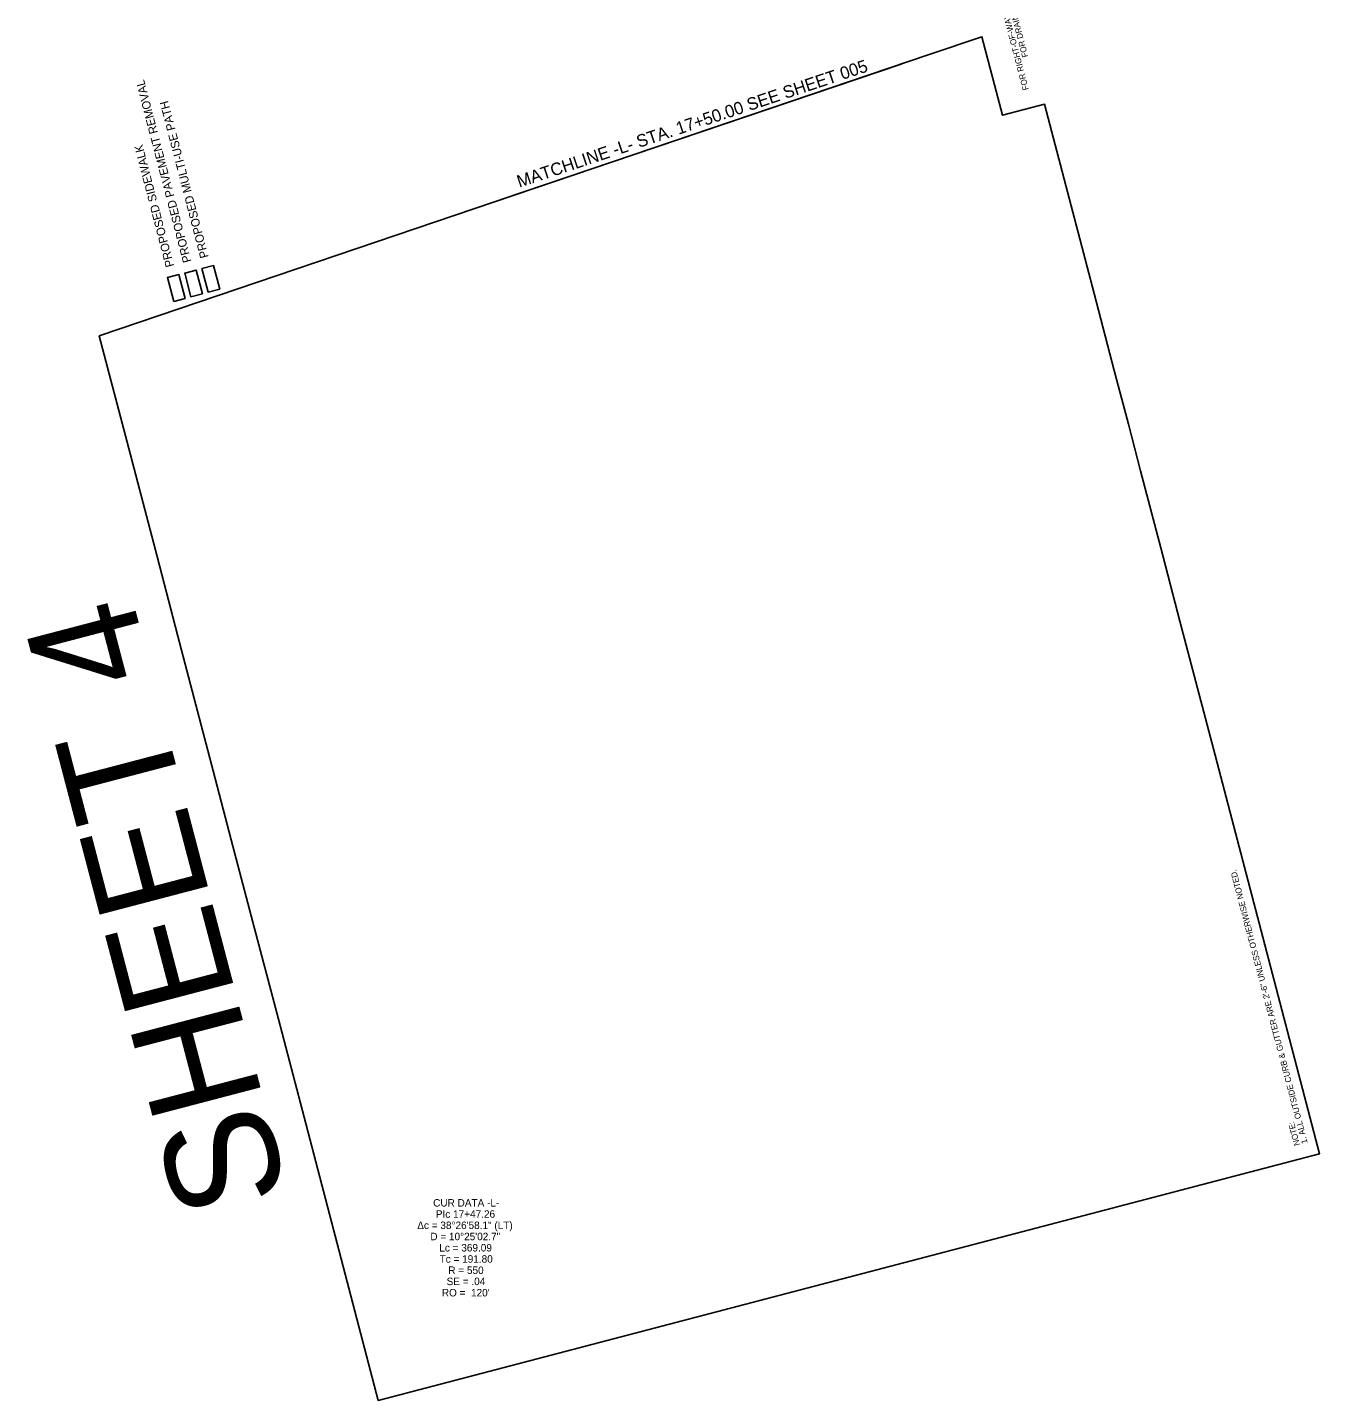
# Model space of a CAD drawing. Extents: x 1366798 to 1369150, y 878329 to 881399.
# Drawn here: x 1366798 to 1368093, y 878329 to 879705 of the extents above; entities that cross this region are included whole.
import ezdxf

# ---------------------------------------------------------------- set-up
doc = ezdxf.new("R2010")
doc.units = 0
for name, color, linetype in [('Matchline Text', 7, 'Continuous'), ('P_NCDOT_Horizontal_Alignment_Station_Label', 7, 'Continuous'), ('P_NCDOT_Horizontal_Alignment_Station_Major_Label', 7, 'Continuous'), ('P_NCDOT_Horizontal_Alignment_Tick_Large', 7, 'Continuous'), ('Prop Conc Curb and Gutter', 7, 'Continuous'), ('Prop Dimension', 7, 'Continuous'), ('Prop Horizontal Alignment Station Label', 7, 'Continuous'), ('Prop Lane Arrow CELL', 7, 'Continuous'), ('Prop Superelevation  Arrow CELL', 7, 'Continuous'), ('Prop Superelevation Label', 7, 'Continuous')]:
    doc.layers.add(name, color=color, linetype=linetype)

msp = doc.modelspace()

# ---------------------------------------------------------------- linework, layer by layer
at = {"layer": 'Matchline Text'}
msp.add_lwpolyline([(1366944.6, 879430.5), (1366938.4, 879454.3), (1366949.8, 879457.4), (1366956.1, 879433.5)], close=True, dxfattribs=at)
at = {"layer": 'P_NCDOT_Horizontal_Alignment_Station_Label'}
msp.add_line((1367272.7, 879532.4), (1367673.5, 879668.2), dxfattribs=at)
at = {"layer": 'P_NCDOT_Horizontal_Alignment_Station_Major_Label'}
msp.add_lwpolyline([(1366979.2, 879439.6), (1366972.9, 879463.4), (1366984.4, 879466.4), (1366990.7, 879442.6)], close=True, dxfattribs=at)
at = {"layer": 'Prop Dimension'}
msp.add_lwpolyline([(1367149.6, 878329.3), (1368092.9, 878576.5), (1368038.1, 878785.7), (1367988.2, 878975.7), (1367953, 879110.2), (1367933.7, 879183.7), (1367913.5, 879260.8), (1367901.3, 879307.5), (1367887.2, 879361.2), (1367867, 879438.3), (1367817.3, 879628), (1367775.2, 879617), (1367754.6, 879695.6), (1367701.6, 879677.7), (1366870, 879396.1), (1366899.6, 879283.2), (1366928, 879174.9), (1366948.9, 879095), (1366966.9, 879026.2), (1366984.3, 878960.1), (1367002.3, 878891.2), (1367024, 878808.6), (1367049.5, 878711.3), (1367075.2, 878613.1)], close=True, dxfattribs=at)
msp.add_lwpolyline([(1367149.6, 878329.3), (1368092.9, 878576.5), (1368038.1, 878785.7), (1367988.2, 878975.7), (1367953, 879110.2), (1367933.7, 879183.7), (1367913.5, 879260.8), (1367901.3, 879307.5), (1367887.2, 879361.2), (1367867, 879438.3), (1367817.3, 879628), (1367775.2, 879617), (1367754.6, 879695.6), (1367701.6, 879677.7), (1366870, 879396.1), (1366899.6, 879283.2), (1366928, 879174.9), (1366948.9, 879095), (1366966.9, 879026.2), (1366984.3, 878960.1), (1367002.3, 878891.2), (1367024, 878808.6), (1367049.5, 878711.3), (1367075.2, 878613.1)], close=True, dxfattribs=at)
at = {"layer": 'Prop Horizontal Alignment Station Label'}
msp.add_lwpolyline([(1366979.2, 879439.6), (1366972.9, 879463.4), (1366984.4, 879466.4), (1366990.7, 879442.6)], close=True, dxfattribs=at)
at = {"layer": 'Prop Lane Arrow CELL'}
msp.add_lwpolyline([(1366961.9, 879435.1), (1366955.7, 879458.9), (1366967.1, 879461.9), (1366973.4, 879438.1)], close=True, dxfattribs=at)

# ---------------------------------------------------------------- texts
at = {"layer": 'P_NCDOT_Horizontal_Alignment_Tick_Large'}
for s, p in [('CUR DATA -L-', (1367204.6, 878523.6)), ('PIc 17+47.26', (1367207.3, 878512.4)), ('Δc = 38°26\'58.1" (LT)', (1367188.7, 878501.1)), ('D = 10°25\'02.7"', (1367201.8, 878489.9)), ('Lc = 369.09', (1367210.8, 878478.6)), ('Tc = 191.80', (1367211.1, 878467.4)), ('R = 550', (1367219.8, 878456.1)), ('SE = .04', (1367218.1, 878444.9)), ("RO =  120'", (1367213.3, 878433.6))]:
    msp.add_text(s, height=7.5, dxfattribs=at).set_placement(p)
at = {"layer": 'Prop Conc Curb and Gutter'}
msp.add_text('MATCHLINE -L- STA. 17+50.00 SEE SHEET 005', height=12.5, rotation=18.4634, dxfattribs=at).set_placement((1367291, 879544.2))
at = {"layer": 'Prop Dimension'}
msp.add_text('SHEET 4', height=112.11, rotation=104.6851, dxfattribs=at).set_placement((1367060.1, 878534.4))
at = {"layer": 'Prop Superelevation  Arrow CELL'}
for s, p in [('FOR RIGHT-OF-WAY STATIONS AND OFFSETS, SEE SHEET 2B-1', (1367801.5, 879642.9)), ('FOR DRAINAGE DETAILS, SEE SHEETS 2D-1 THRU 2D-2', (1367801, 879675.8)), ('1. ALL OUTSIDE CURB & GUTTER ARE 2\'-6" UNLESS OTHERWISE NOTED.', (1368081, 878587.5)), ('NOTE:', (1368073.3, 878585.5))]:
    msp.add_text(s, height=6, rotation=104.6851, dxfattribs=at).set_placement(p)
at = {"layer": 'Prop Superelevation Label'}
for s, p in [('PROPOSED PAVEMENT REMOVAL', (1366962.4, 879470.5)), ('PROPOSED MULTI-USE PATH', (1366979.7, 879475)), ('PROPOSED SIDEWALK', (1366945.1, 879466))]:
    msp.add_text(s, height=8.5, rotation=104.5986, dxfattribs=at).set_placement(p)

doc.saveas('drawing.dxf')
